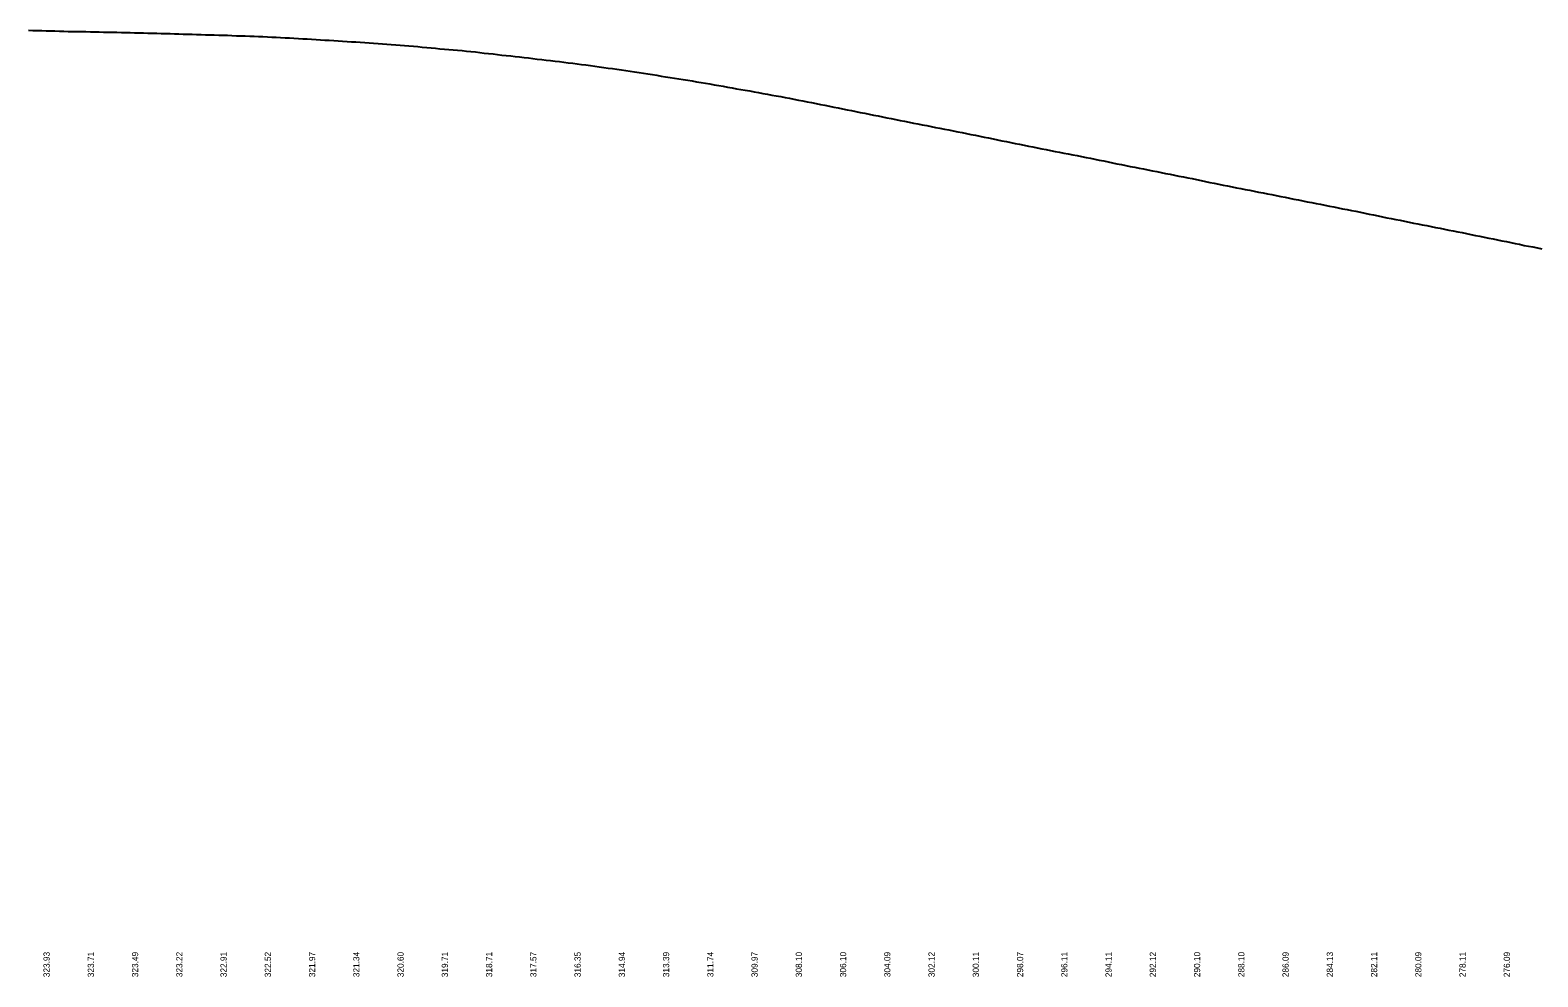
# Model space of a CAD drawing. Extents: x 1838386 to 1955906, y 719739 to 834437.
# Drawn here: x 1881790 to 1883494, y 823142 to 824212 of the extents above; entities that cross this region are included whole.
import ezdxf

# ---------------------------------------------------------------- set-up
doc = ezdxf.new("R2010")
doc.units = 0
doc.layers.add('RD_DDB_Profile_EX', color=7, linetype='Continuous')
doc.layers.add('RD_DDB_StripGrade', color=7, linetype='Continuous')

msp = doc.modelspace()

# ---------------------------------------------------------------- linework, layer by layer
at = {"layer": 'RD_DDB_Profile_EX'}
for points in [[(1881788.1, 824212.1), (1881793.1, 824211.8), (1881798.1, 824211.8), (1881803.1, 824211.6), (1881808.1, 824211.4), (1881813.1, 824211.3), (1881818.1, 824211.1), (1881823.1, 824211), (1881828.1, 824210.8), (1881833.1, 824210.7), (1881838.1, 824210.6), (1881843.1, 824210.5), (1881848.1, 824210.4), (1881853.1, 824210.4), (1881858.1, 824210.3), (1881863.1, 824210.2)], [(1881863.1, 824210.2), (1881868.1, 824210.1), (1881873.1, 824209.9), (1881878.1, 824209.8), (1881883.1, 824209.7), (1881888.1, 824209.6), (1881893.1, 824209.5), (1881898.1, 824209.4), (1881903.1, 824209.3), (1881908.1, 824209.2), (1881913.1, 824209.1), (1881918.1, 824208.9), (1881923.1, 824208.8), (1881928.1, 824208.7), (1881933.1, 824208.6), (1881938.1, 824208.4), (1881943.1, 824208.3), (1881948.1, 824208.2), (1881953.1, 824208), (1881958.1, 824207.9), (1881963.1, 824207.7), (1881968.1, 824207.6), (1881973.1, 824207.4), (1881978.1, 824207.2), (1881983.1, 824207.1), (1881988.1, 824206.9), (1881993.1, 824206.8), (1881998.1, 824206.6), (1882003.1, 824206.5), (1882008.1, 824206.3), (1882013.1, 824206.2), (1882018.1, 824206), (1882023.1, 824205.8), (1882028.1, 824205.7), (1882033.1, 824205.5), (1882038.1, 824205.3), (1882043.1, 824205.1), (1882048.1, 824204.9), (1882053.1, 824204.7), (1882058.1, 824204.4), (1882063.1, 824204.2), (1882068.1, 824204), (1882073.1, 824203.7), (1882078.1, 824203.5), (1882083.1, 824203.2), (1882088.1, 824203), (1882093.1, 824202.7), (1882098.1, 824202.4), (1882103.1, 824202.1), (1882108.1, 824201.8), (1882113.1, 824201.5), (1882118.1, 824201.2), (1882123.1, 824200.9), (1882128.1, 824200.6), (1882133.1, 824200.3), (1882138.1, 824200), (1882143.1, 824199.7), (1882148.1, 824199.3), (1882153.1, 824199), (1882158.1, 824198.7), (1882163.1, 824198.3), (1882168.1, 824198), (1882173.1, 824197.7), (1882178.1, 824197.3), (1882183.1, 824196.9), (1882188.1, 824196.5), (1882193.1, 824196.2), (1882198.1, 824195.8), (1882203.1, 824195.4), (1882208.1, 824195.1), (1882213.1, 824194.6), (1882218.1, 824194.2), (1882223.1, 824193.8), (1882228.1, 824193.4), (1882233.1, 824192.9), (1882238.1, 824192.5), (1882243.1, 824192.1), (1882248.1, 824191.6), (1882253.1, 824191.1), (1882258.1, 824190.6), (1882263.1, 824190.2), (1882268.1, 824189.7), (1882273.1, 824189.3), (1882278.1, 824188.9), (1882283.1, 824188.3), (1882288.1, 824187.9), (1882293.1, 824187.4), (1882298.1, 824186.8), (1882303.1, 824186.2), (1882308.1, 824185.7), (1882313.1, 824185.2), (1882318.1, 824184.6), (1882323.1, 824183.9), (1882328.1, 824183.4), (1882333.1, 824182.9), (1882338.1, 824182.3), (1882343.1, 824181.8), (1882348.1, 824181.2), (1882353.1, 824180.7), (1882358.1, 824180.1), (1882363.1, 824179.4)], [(1882363.1, 824179.4), (1882368.1, 824178.9), (1882373.1, 824178.3), (1882378.1, 824177.8), (1882383.1, 824177.1), (1882388.1, 824176.5), (1882393.1, 824175.9), (1882398.1, 824175.2), (1882403.1, 824174.6), (1882408.1, 824174), (1882413.1, 824173.4), (1882418.1, 824172.7), (1882423.1, 824172.1), (1882428.1, 824171.4), (1882433.1, 824170.7), (1882438.1, 824169.9), (1882443.1, 824169.2), (1882448.1, 824168.6), (1882453.1, 824167.9), (1882458.1, 824167.1), (1882463.1, 824166.3), (1882468.1, 824165.6), (1882473.1, 824164.9), (1882478.1, 824164.1), (1882483.1, 824163.4), (1882488.1, 824162.5), (1882493.1, 824161.8), (1882498.1, 824161), (1882503.1, 824160.2), (1882508.1, 824159.4), (1882513.1, 824158.6), (1882518.1, 824157.8), (1882523.1, 824157), (1882528.1, 824156.2), (1882533.1, 824155.4), (1882538.1, 824154.6), (1882543.1, 824153.7), (1882548.1, 824152.9), (1882553.1, 824152), (1882558.1, 824151.2), (1882563.1, 824150.3), (1882568.1, 824149.5), (1882573.1, 824148.6), (1882578.1, 824147.6), (1882583.1, 824146.8), (1882588.1, 824145.9), (1882593.1, 824145.1), (1882598.1, 824144.2), (1882603.1, 824143.3), (1882608.1, 824142.4), (1882613.1, 824141.5), (1882618.1, 824140.5), (1882623.1, 824139.7), (1882628.1, 824138.7), (1882633.1, 824137.8), (1882638.1, 824136.9), (1882643.1, 824135.9), (1882648.1, 824135), (1882653.1, 824134.1), (1882658.1, 824133), (1882663.1, 824132.1), (1882668.1, 824131.2), (1882673.1, 824130.1), (1882678.1, 824129.2), (1882683.1, 824128.2), (1882688.1, 824127.2), (1882693.1, 824126.2), (1882698.1, 824125.1), (1882703.1, 824124.1), (1882708.1, 824123.1), (1882713.1, 824122.1), (1882718.1, 824121.1), (1882723.1, 824120.2), (1882728.1, 824119.1), (1882733.1, 824118.1), (1882738.1, 824117.1), (1882743.1, 824116), (1882748.1, 824115.1), (1882753.1, 824114), (1882758.1, 824113.1), (1882763.1, 824112.1), (1882768.1, 824111.1), (1882773.1, 824110.1), (1882778.1, 824109.1), (1882783.1, 824108.1), (1882788.1, 824107.1), (1882793.1, 824106.2), (1882798.1, 824105.1), (1882803.1, 824104.2), (1882808.1, 824103.2), (1882813.1, 824102.2), (1882818.1, 824101.3), (1882823.1, 824100.2), (1882828.1, 824099.2), (1882833.1, 824098.3), (1882838.1, 824097.2), (1882843.1, 824096.2), (1882848.1, 824095.3), (1882853.1, 824094.2), (1882858.1, 824093.2), (1882863.1, 824092.2)], [(1882863.1, 824092.2), (1882868.1, 824091.2), (1882873.1, 824090.2), (1882878.1, 824089.2), (1882883.1, 824088.1), (1882888.1, 824087.1), (1882893.1, 824086.1), (1882898.1, 824085.1), (1882903.1, 824084), (1882908.1, 824083), (1882913.1, 824082), (1882918.1, 824081), (1882923.1, 824080), (1882928.1, 824079), (1882933.1, 824078), (1882938.1, 824077), (1882943.1, 824076), (1882948.1, 824075), (1882953.1, 824074.1), (1882958.1, 824073.1), (1882963.1, 824072.1), (1882968.1, 824071.1), (1882973.1, 824070.2), (1882978.1, 824069.1), (1882983.1, 824068.2), (1882988.1, 824067.2), (1882993.1, 824066.2), (1882998.1, 824065.2), (1883003.1, 824064.2), (1883008.1, 824063.2), (1883013.1, 824062.2), (1883018.1, 824061.1), (1883023.1, 824060.2), (1883028.1, 824059.2), (1883033.1, 824058.1), (1883038.1, 824057.1), (1883043.1, 824056.2), (1883048.1, 824055.2), (1883053.1, 824054.1), (1883058.1, 824053.2), (1883063.1, 824052.2), (1883068.1, 824051.2), (1883073.1, 824050.1), (1883078.1, 824049.1), (1883083.1, 824048.2), (1883088.1, 824047.1), (1883093.1, 824046.2), (1883098.1, 824045.2), (1883103.1, 824044.2), (1883108.1, 824043.1), (1883113.1, 824042.1), (1883118.1, 824041.1), (1883123.1, 824040), (1883128.1, 824039.1), (1883133.1, 824038.1), (1883138.1, 824037), (1883143.1, 824036.1), (1883148.1, 824034.9), (1883153.1, 824034), (1883158.1, 824033), (1883163.1, 824032.1), (1883168.1, 824031.1), (1883173.1, 824030.1), (1883178.1, 824029.1), (1883183.1, 824028.1), (1883188.1, 824027), (1883193.1, 824026.1), (1883198.1, 824025.1), (1883203.1, 824024.2), (1883208.1, 824023.1), (1883213.1, 824022.1), (1883218.1, 824021.2), (1883223.1, 824020.2), (1883228.1, 824019.1), (1883233.1, 824018.1), (1883238.1, 824017.2), (1883243.1, 824016.2), (1883248.1, 824015.2), (1883253.1, 824014.2), (1883258.1, 824013.2), (1883263.1, 824012.3), (1883268.1, 824011.2), (1883273.1, 824010.2), (1883278.1, 824009.2), (1883283.1, 824008.3), (1883288.1, 824007.3), (1883293.1, 824006.2), (1883298.1, 824005.3), (1883303.1, 824004.2), (1883308.1, 824003.2), (1883313.1, 824002.2), (1883318.1, 824001.1), (1883323.1, 824000), (1883328.1, 823999.1), (1883333.1, 823998.2), (1883338.1, 823997.1), (1883343.1, 823996.1), (1883348.1, 823995.1), (1883353.1, 823994), (1883358.1, 823993), (1883363.1, 823992.1)], [(1883363.1, 823992.1), (1883368.1, 823991.1), (1883373.1, 823990), (1883378.1, 823989.1), (1883383.1, 823988.1), (1883388.1, 823987.1), (1883393.1, 823986.1), (1883398.1, 823985.1), (1883403.1, 823984.2), (1883408.1, 823983.2), (1883413.1, 823982.2), (1883418.1, 823981.2), (1883423.1, 823980.1), (1883428.1, 823979.2), (1883433.1, 823978.2), (1883438.1, 823977.1), (1883443.1, 823976.2), (1883448.1, 823975.1), (1883453.1, 823974.1), (1883458.1, 823973.1), (1883463.1, 823972.1), (1883468.1, 823971), (1883473.1, 823970), (1883478.1, 823968.8), (1883483.1, 823968), (1883488.1, 823967), (1883493.1, 823966), (1883498.1, 823965)]]:
    msp.add_lwpolyline(points, dxfattribs=at)

# ---------------------------------------------------------------- texts
at = {"layer": 'RD_DDB_StripGrade'}
for s, p in [('323.93', (1881812.1, 823141.6)), ('323.71', (1881862.1, 823141.6)), ('323.49', (1881912.1, 823141.6)), ('323.22', (1881962.1, 823141.6)), ('322.91', (1882012.1, 823141.6)), ('322.52', (1882062.1, 823141.6)), ('321.97', (1882112.1, 823141.6)), ('321.34', (1882162.1, 823141.6)), ('320.60', (1882212.1, 823141.6)), ('319.71', (1882262.1, 823141.6)), ('318.71', (1882312.1, 823141.6)), ('317.57', (1882362.1, 823141.6)), ('316.35', (1882412.1, 823141.6)), ('314.94', (1882462.1, 823141.6)), ('313.39', (1882512.1, 823141.6)), ('311.74', (1882562.1, 823141.6)), ('309.97', (1882612.1, 823141.6)), ('308.10', (1882662.1, 823141.6)), ('306.10', (1882712.1, 823141.6)), ('304.09', (1882762.1, 823141.6)), ('302.12', (1882812.1, 823141.6)), ('300.11', (1882862.1, 823141.6)), ('298.07', (1882912.1, 823141.6)), ('296.11', (1882962.1, 823141.6)), ('294.11', (1883012.1, 823141.6)), ('292.12', (1883062.1, 823141.6)), ('290.10', (1883112.1, 823141.6)), ('288.10', (1883162.1, 823141.6)), ('286.09', (1883212.1, 823141.6)), ('284.13', (1883262.1, 823141.6)), ('282.11', (1883312.1, 823141.6)), ('280.09', (1883362.1, 823141.6)), ('278.11', (1883412.1, 823141.6)), ('276.09', (1883462.1, 823141.6))]:
    msp.add_text(s, height=7, rotation=90, dxfattribs=at).set_placement(p)

doc.saveas('drawing.dxf')
